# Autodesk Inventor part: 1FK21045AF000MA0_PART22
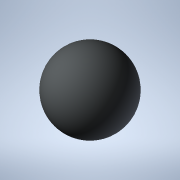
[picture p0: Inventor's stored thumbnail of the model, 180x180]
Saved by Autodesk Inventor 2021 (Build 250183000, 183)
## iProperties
Created: 2025-04
Part Number: 1FK21045AF000MA0_PART22
Material: Generic
Catalog Web Link: www.3dfindit.com
Description: -Servo synchronous motor
Document SubType Name: Modeling
Designer: psAdmin
Mass: 0.137258 g
Surface Area: 1.2868 cm^2
Volume: 0.137258 cm^3
Density: 1 g/cm^3
Appearance: PSOLRGB-212-217-219
Category: PARTsolutions
Title: 1FK21045AF000MA0_PART22
Author: Cadenas PARTsolutions
Comments: Servo synchronous motor
Sending System: PARTsolutions
Preprocessor: ST-DEVELOPER v19.3
PSOL_IDENT_0: {$CADENAS_DATA/23d-libs/siemens_ag/_cat_/8b/0a/1fk21045af000ma0.prj},216 {VTYP=3D},{NB=1FK21045AF000
PSOL_IDENT_1: MA0_PART22},{LINA=1FK21045AF000MA0_PART22},{NN=1FK21045AF000MA0_PART22},{NOPRJ=TRUE},{DATE=19.08.202
PSOL_IDENT_2: 5 14:00:48},{GEOMDATE=30.07.2025 02:00:28},{VERSION=},{LINEID=10},{WBVAR=},{WBNUMERIC=}  {NB=1FK2104
PSOL_IDENT_3: 5AF000MA0_PART22},{LINA=1FK21045AF000MA0_PART22},{KT=DUMMY},{PREVIEW=../../../_pool_/a9/69/p_d211_xx
PSOL_IDENT_4: _00818j.png},{DESCSHORT=SIMOTICS S-1FK2 HD, SINAMICS S210 3AC 400V-480V, 2.4 Nm, 3000 rpm},{DESCLONG=
PSOL_IDENT_5: SIMOTICS S-1FK2 HD servo motor M0=2.4 Nm; PN = 0.75 kW at nN=3000 rpm (380-480 V); PN = 0.375 kW at
PSOL_IDENT_6: nN=1500 rpm (200-240 V); degree of protection IP64; cylindrical shaft D19x40mm; absolute encoder 22-
PSOL_IDENT_7: bit + 12-bit multiturn (encoder AM22DQC); with OCC interface; plug size M17, rotatable; SIMOTICS S-1
PSOL_IDENT_8: FK2 servomotorfor a wide range of uses in industrial environments. SIMOTICS S‑1FK2 servomotors are c
PSOL_IDENT_9: ompact synchronous motors with a high dynamic performance that set themselves apart as a result of t
PSOL_IDENT_10: heir high power density, degree of protection and overload capability. The motors are available in t
PSOL_IDENT_11: wo variants: as High Dynamic variant (highest dynamic performance as a result of the low intrinsic m
PSOL_IDENT_12: oment of inertia for applications demanding a high dynamic performance with low moved masses) - and
PSOL_IDENT_13: as Compact variant (precise and stable closed-loop control for medium up to large moved masses as a
PSOL_IDENT_14: result of a medium intrinsic moment of inertia). SIMOTICSS‑1FK2 servomotors fully exploit their stre
PSOL_IDENT_15: ngths in a system with the SINAMICSS210 frequency converter and simple connection using the one cabl
PSOL_IDENT_16: e connection (OCC). Advantages include the short control and positioning times, fast and precise cor
PSOL_IDENT_17: rection of disturbing quantities as well as stable control with a high dynamic performance. The serv
PSOL_IDENT_18: o motors can be configured to address a wide range of requirements. For example with and without hol
PSOL_IDENT_19: ding brake, IP64 or IP65 degree of protection, singleturn or multiturn absolute encoders - to name j
PSOL_IDENT_20: ust a few. Further, the servomotors are available in different shaft heights extending from 20 to 10
PSOL_IDENT_21: 0. A shaft sealing ring is available to achieve an IP65 degree of protection and for subsequent moun
PSOL_IDENT_22: ting at the motor or as spare part. SIMOTICS - the optimum motor for each and every motion control a
PSOL_IDENT_23: pplication.},{INTNO=195125050112},{SUPPLIERALTNO=1FK2104-5AF00-0MA0},{MANUID=1FK21045AF000MA0},{MANU
PSOL_IDENT_24: NAME=Siemens},{MANUTYPEDESC=Synchronous motor 1FK2-HD 2.4 NM},{AAU732=SIMOTICS},{AAO057=S-1FK2},{AAU
PSOL_IDENT_25: 734=SIMOTICS S-1FK2 HD servo motor M0=2.4 Nm; PN = 0.75 kW at nN=3000 rpm (380-480 V); PN = 0.375 kW
PSOL_IDENT_26: at nN=1500 rpm (200-240 V); degree of protection IP64; cylindrical shaft D19x40mm; absolute encoder
PSOL_IDENT_27: 22-bit + 12-bit multiturn (encoder AM22DQC); with OCC interface; plug size M17, rotatable;},{AAW338=
PSOL_IDENT_28: Synchronous motor 1FK2-HD 2.4 NM},{AAO742=SIMOTICS},{AAO663=4042948692912},{NOCUPEROU=1},{PRICEQUANT
PSOL_IDENT_29: ITY=1},{QUANTITYMIN=1},{QUANTITYINT=1},{CTN=85015100},{COO=DE},{AAO676=1FK2104-5AF00-0MA0},{AAO677=S
PSOL_IDENT_30: iemens AG},{ORDERUNIT=C62},{CONTENTUNIT=C62}
NB: 1FK21045AF000MA0_PART22
NT: Servo synchronous motor
NBSYN: $MANUID._PART22
LINA: 1FK21045AF000MA0_PART22
CATALOG: SIEMENS
PREVIEW: ../../../_pool_/a9/69/p_d211_xx_00818j.png
DESCSHORT: SIMOTICS S-1FK2 HD, SINAMICS S210 3AC 400V-480V, 2.4 Nm, 3000 rpm
DESCLONG: SIMOTICS S-1FK2 HD servo motor M0=2.4 Nm; PN = 0.75 kW at nN=3000 rpm (380-480 V); PN = 0.375 kW at nN=1500 rpm (200-240 V); degree of protection IP64; cylindri
INTNO: 195125050112
SUPPLIERALTNO: 1FK2104-5AF00-0MA0
MANUID: 1FK21045AF000MA0
MANUNAME: Siemens
MANUTYPEDESC: Synchronous motor 1FK2-HD 2.4 NM
AAU732: SIMOTICS
AAO057: S-1FK2
AAU734: SIMOTICS S-1FK2 HD servo motor M0=2.4 Nm; PN = 0.75 kW at nN=3000 rpm (380-480 V); PN = 0.375 kW at nN=1500 rpm (200-240 V); degree of protection IP64; cylindri
AAW338: Synchronous motor 1FK2-HD 2.4 NM
AAO742: SIMOTICS
AAO663: 4042948692912.0
NOCUPEROU: 1
PRICEQUANTITY: 1
QUANTITYMIN: 1
QUANTITYINT: 1
CTN: 85015100
COO: DE
ARTICLENO: 1FK21045AF000MA0_PART22
BOMINFO: 1FK21045AF000MA0_PART22
CREATOR: CADENAS GmbH
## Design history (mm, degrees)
feature "2025_04_17_15_40_42_0766"
body "Solid1"
